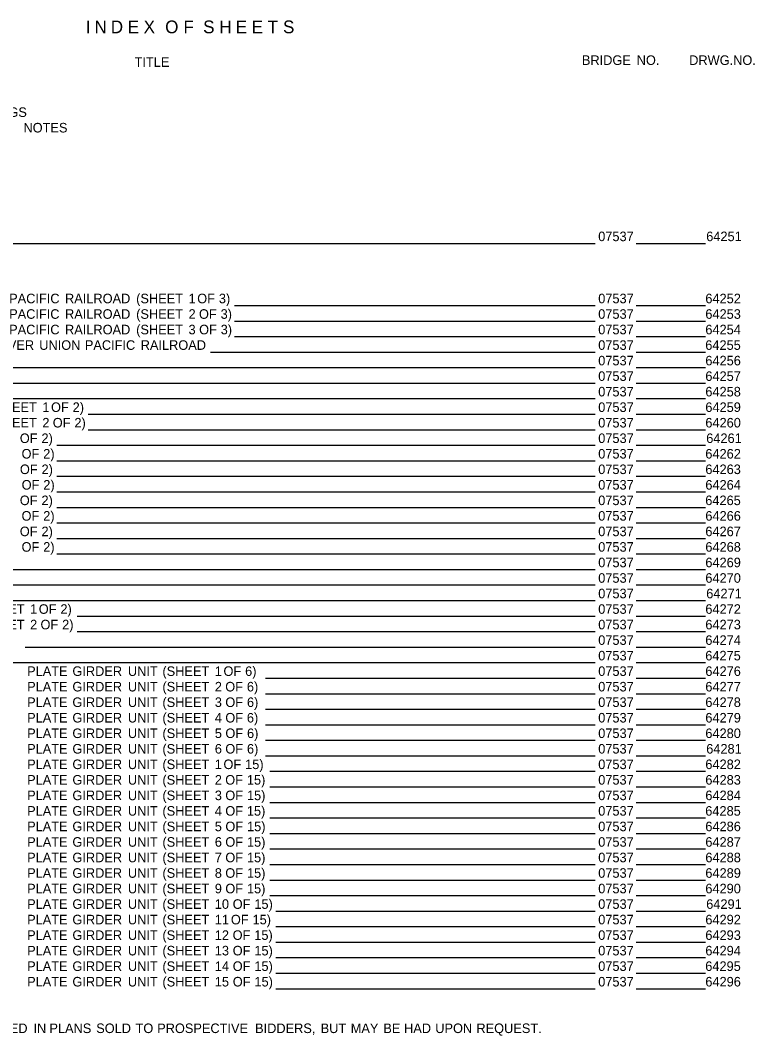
# Model space of a CAD drawing. Extents: x -1420 to 1630, y -1031 to 935.
# Drawn here: x -917 to 5, y -757 to 518 of the extents above; entities that cross this region are included whole.
import ezdxf

# ---------------------------------------------------------------- set-up
doc = ezdxf.new("R2010")
doc.units = 0
doc.layers.add('Default', color=7, linetype='Continuous')

msp = doc.modelspace()

# ---------------------------------------------------------------- linework, layer by layer
at = {"layer": 'Default'}
for p, q in [((-994.1, 238), (-195.2, 238)), ((-143.5, 238), (-56.7, 238)), ((-648.5, 160), (-195.2, 160)), ((-143.5, 160), (-56.7, 160)), ((-648.5, 140.5), (-195.2, 140.5)), ((-143.5, 140.5), (-56.7, 140.5)), ((-648.5, 121), (-195.2, 121)), ((-143.5, 121), (-56.7, 121)), ((-678.6, 101.5), (-195.2, 101.5)), ((-143.5, 101.5), (-56.7, 101.5)), ((-964.8, 82), (-195.2, 82)), ((-143.5, 82), (-56.7, 82)), ((-964.8, 62.5), (-195.2, 62.5)), ((-143.5, 62.5), (-56.7, 62.5)), ((-964.8, 43), (-195.2, 43)), ((-143.5, 43), (-56.7, 43)), ((-832.1, 23.5), (-195.2, 23.5)), ((-143.5, 23.5), (-56.7, 23.5)), ((-832.1, 4), (-195.2, 4)), ((-143.5, 4), (-56.7, 4)), ((-871.6, -15.5), (-195.2, -15.5)), ((-143.5, -15.5), (-56.7, -15.5)), ((-871.6, -35), (-195.2, -35)), ((-143.5, -35), (-56.7, -35)), ((-871.6, -54.5), (-195.2, -54.5)), ((-143.5, -54.5), (-56.7, -54.5)), ((-871.6, -74), (-195.2, -74)), ((-143.5, -74), (-56.7, -74)), ((-871.6, -93.5), (-195.2, -93.5)), ((-143.5, -93.5), (-56.7, -93.5)), ((-871.6, -113), (-195.2, -113)), ((-143.5, -113), (-56.7, -113)), ((-871.6, -132.5), (-195.2, -132.5)), ((-143.5, -132.5), (-56.7, -132.5)), ((-871.6, -152), (-195.2, -152)), ((-143.5, -152), (-56.7, -152)), ((-960.5, -171.5), (-195.2, -171.5)), ((-143.5, -171.5), (-56.7, -171.5)), ((-960.5, -191), (-195.2, -191)), ((-143.5, -191), (-56.7, -191)), ((-960.5, -210.5), (-195.2, -210.5)), ((-143.5, -210.5), (-56.7, -210.5)), ((-846.1, -230), (-195.2, -230)), ((-143.5, -230), (-56.7, -230)), ((-846.1, -249.5), (-195.2, -249.5)), ((-143.5, -249.5), (-56.7, -249.5)), ((-911.2, -269), (-195.2, -269)), ((-143.5, -269), (-56.7, -269)), ((-1055.5, -288.5), (-195.2, -288.5)), ((-143.5, -288.5), (-56.7, -288.5)), ((-609.3, -308), (-195.2, -308)), ((-143.5, -308), (-56.7, -308)), ((-609.3, -327.5), (-195.2, -327.5)), ((-143.5, -327.5), (-56.7, -327.5)), ((-609.3, -347), (-195.2, -347)), ((-143.5, -347), (-56.7, -347)), ((-609.3, -366.5), (-195.2, -366.5)), ((-143.5, -366.5), (-56.7, -366.5)), ((-609.3, -386), (-195.2, -386)), ((-143.5, -386), (-56.7, -386)), ((-609.3, -405.5), (-195.2, -405.5)), ((-143.5, -405.5), (-56.7, -405.5)), ((-603.8, -425), (-195.2, -425)), ((-143.5, -425), (-56.7, -425)), ((-603.8, -444.5), (-195.2, -444.5)), ((-143.5, -444.5), (-56.7, -444.5)), ((-603.8, -464), (-195.2, -464)), ((-143.5, -464), (-56.7, -464)), ((-603.8, -483.5), (-195.2, -483.5)), ((-143.5, -483.5), (-56.7, -483.5)), ((-603.8, -503), (-195.2, -503)), ((-143.5, -503), (-56.7, -503)), ((-603.8, -522.5), (-195.2, -522.5)), ((-143.5, -522.5), (-56.7, -522.5)), ((-603.8, -542), (-195.2, -542)), ((-143.5, -542), (-56.7, -542)), ((-603.8, -561.5), (-195.2, -561.5)), ((-143.5, -561.5), (-56.7, -561.5)), ((-603.8, -581), (-195.2, -581)), ((-143.5, -581), (-56.7, -581)), ((-596.3, -600.5), (-195.2, -600.5)), ((-143.5, -600.5), (-56.7, -600.5)), ((-596.3, -620), (-195.2, -620)), ((-143.5, -620), (-56.7, -620)), ((-596.3, -639.5), (-195.2, -639.5)), ((-143.5, -639.5), (-56.7, -639.5)), ((-596.3, -659), (-195.2, -659)), ((-143.5, -659), (-56.7, -659)), ((-596.3, -678.5), (-195.2, -678.5)), ((-143.5, -678.5), (-56.7, -678.5)), ((-596.3, -698), (-195.2, -698)), ((-143.5, -698), (-56.7, -698))]:
    msp.add_line(p, q, dxfattribs=at)

# ---------------------------------------------------------------- texts
for s, height, p in [('I', 16, (-835, 501.9)), (' N', 16, (-830.2, 501.9)), (' D', 16, (-809.7, 501.9)), (' E', 16, (-788.4, 501.9)), (' X', 16, (-768.4, 501.9)), ('  O', 16, (-747.3, 501.9)), (' F', 16, (-718.4, 501.9)), ('  S', 16, (-699.6, 501.9)), (' H', 16, (-673.3, 501.9)), (' E', 16, (-652.7, 501.9)), (' E', 16, (-632.7, 501.9)), (' T', 16, (-612.7, 501.9)), (' S', 16, (-593.3, 501.9)), ('BRIDGE', 12, (-211.8, 462.1)), (' NO.', 12, (-147.4, 462.1)), ('DRWG.NO.', 12, (-77, 462.1)), ('TITLE', 12, (-773.8, 459.7)), (' DRAWINGS', 12, (-1001.9, 396.8)), (' NOTES', 12, (-917.9, 377.3)), ('07537', 12, (-191.3, 240.8)), ('64251', 12, (-55.6, 240.8)), (' PACIFIC', 12, (-935.9, 162.8)), (' RAILROAD', 12, (-865.7, 162.8)), (' (SHEET', 12, (-776.3, 162.8)), (' 1', 12, (-710.5, 162.8)), (' OF', 12, (-699.6, 162.8)), (' 3)', 12, (-672.4, 162.8)), ('07537', 12, (-191.3, 162.8)), ('64252', 12, (-56.7, 162.8)), (' PACIFIC', 12, (-935.9, 143.3)), (' RAILROAD', 12, (-865.7, 143.3)), (' (SHEET', 12, (-776.3, 143.3)), (' 2', 12, (-710.5, 143.3)), (' OF', 12, (-697.4, 143.3)), (' 3)', 12, (-670.2, 143.3)), ('07537', 12, (-191.3, 143.3)), ('64253', 12, (-56.7, 143.3)), (' PACIFIC', 12, (-935.9, 123.8)), (' RAILROAD', 12, (-865.7, 123.8)), (' (SHEET', 12, (-776.3, 123.8)), (' 3', 12, (-710.5, 123.8)), (' OF', 12, (-697.2, 123.8)), (' 3)', 12, (-670.1, 123.8)), ('07537', 12, (-191.3, 123.8)), ('64254', 12, (-56.7, 123.8)), (' OVER', 12, (-950, 104.3)), (' UNION', 12, (-898.1, 104.3)), (' PACIFIC', 12, (-840.8, 104.3)), (' RAILROAD', 12, (-770.6, 104.3)), ('07537', 12, (-191.3, 104.3)), ('64255', 12, (-56.8, 104.3)), ('07537', 12, (-191.3, 84.8)), ('64256', 12, (-56.7, 84.8)), ('07537', 12, (-191.3, 65.3)), ('64257', 12, (-56.7, 65.3)), ('07537', 12, (-191.3, 45.8)), ('64258', 12, (-56.7, 45.8)), (' (SHEET', 12, (-960, 26.3)), (' 1', 12, (-894.2, 26.3)), (' OF', 12, (-883.3, 26.3)), (' 2)', 12, (-856.1, 26.3)), ('07537', 12, (-191.3, 26.3)), ('64259', 12, (-56.7, 26.3)), (' (SHEET', 12, (-960, 6.8)), (' 2', 12, (-894.2, 6.8)), (' OF', 12, (-881.1, 6.8)), (' 2)', 12, (-853.9, 6.8)), ('07537', 12, (-191.3, 6.8)), ('64260', 12, (-56.7, 6.8)), (' OF', 12, (-922.5, -12.7)), (' 2)', 12, (-895.3, -12.7)), ('07537', 12, (-191.3, -12.7)), ('64261', 12, (-55.6, -12.7)), (' OF', 12, (-920.3, -32.2)), (' 2)', 12, (-893.1, -32.2)), ('07537', 12, (-191.3, -32.2)), ('64262', 12, (-56.7, -32.2)), (' OF', 12, (-922.4, -51.7)), (' 2)', 12, (-895.2, -51.7)), ('07537', 12, (-191.3, -51.7)), ('64263', 12, (-56.7, -51.7)), (' OF', 12, (-920.2, -71.2)), (' 2)', 12, (-893, -71.2)), ('07537', 12, (-191.3, -71.2)), ('64264', 12, (-56.7, -71.2)), (' OF', 12, (-922.5, -90.7)), (' 2)', 12, (-895.3, -90.7)), ('07537', 12, (-191.3, -90.7)), ('64265', 12, (-56.8, -90.7)), (' OF', 12, (-920.3, -110.2)), (' 2)', 12, (-893.1, -110.2)), ('07537', 12, (-191.3, -110.2)), ('64266', 12, (-56.7, -110.2)), (' OF', 12, (-922.5, -129.7)), (' 2)', 12, (-895.3, -129.7)), ('07537', 12, (-191.3, -129.7)), ('64267', 12, (-56.7, -129.7)), (' OF', 12, (-920.3, -149.2)), (' 2)', 12, (-893.1, -149.2)), ('07537', 12, (-191.3, -149.2)), ('64268', 12, (-56.7, -149.2)), ('07537', 12, (-191.3, -168.7)), ('64269', 12, (-56.7, -168.7)), ('07537', 12, (-191.3, -188.2)), ('64270', 12, (-56.7, -188.2)), ('07537', 12, (-191.3, -207.7)), ('64271', 12, (-55.6, -207.7)), (' (SHEET', 12, (-975.4, -227.2)), (' 1', 12, (-909.6, -227.2)), (' OF', 12, (-898.7, -227.2)), (' 2)', 12, (-871.5, -227.2)), ('07537', 12, (-191.3, -227.2)), ('64272', 12, (-56.7, -227.2)), (' (SHEET', 12, (-975.4, -246.7)), (' 2', 12, (-909.6, -246.7)), (' OF', 12, (-896.5, -246.7)), (' 2)', 12, (-869.3, -246.7)), ('07537', 12, (-191.3, -246.7)), ('64273', 12, (-56.7, -246.7)), ('07537', 12, (-191.3, -266.2)), ('64274', 12, (-56.7, -266.2)), ('07537', 12, (-191.3, -285.7)), ('64275', 12, (-56.8, -285.7)), (' PLATE', 12, (-913.3, -305.2)), (' GIRDER', 12, (-856.4, -305.2)), (' UNIT', 12, (-786.7, -305.2)), (' (SHEET', 12, (-743.3, -305.2)), (' 1', 12, (-677.5, -305.2)), (' OF', 12, (-666.6, -305.2)), (' 6)', 12, (-639.4, -305.2)), ('07537', 12, (-191.3, -305.2)), ('64276', 12, (-56.7, -305.2)), (' PLATE', 12, (-913.3, -324.7)), (' GIRDER', 12, (-856.4, -324.7)), (' UNIT', 12, (-786.7, -324.7)), (' (SHEET', 12, (-743.3, -324.7)), (' 2', 12, (-677.5, -324.7)), (' OF', 12, (-664.4, -324.7)), (' 6)', 12, (-637.2, -324.7)), ('07537', 12, (-191.3, -324.7)), ('64277', 12, (-56.7, -324.7)), (' PLATE', 12, (-913.3, -344.2)), (' GIRDER', 12, (-856.4, -344.2)), (' UNIT', 12, (-786.7, -344.2)), (' (SHEET', 12, (-743.3, -344.2)), (' 3', 12, (-677.5, -344.2)), (' OF', 12, (-664.3, -344.2)), (' 6)', 12, (-637.1, -344.2)), ('07537', 12, (-191.3, -344.2)), ('64278', 12, (-56.7, -344.2)), (' PLATE', 12, (-913.3, -363.7)), (' GIRDER', 12, (-856.4, -363.7)), (' UNIT', 12, (-786.7, -363.7)), (' (SHEET', 12, (-743.3, -363.7)), (' 4', 12, (-677.5, -363.7)), (' OF', 12, (-664.3, -363.7)), (' 6)', 12, (-637.2, -363.7)), ('07537', 12, (-191.3, -363.7)), ('64279', 12, (-56.7, -363.7)), (' PLATE', 12, (-913.3, -383.2)), (' GIRDER', 12, (-856.4, -383.2)), (' UNIT', 12, (-786.7, -383.2)), (' (SHEET', 12, (-743.3, -383.2)), (' 5', 12, (-677.5, -383.2)), (' OF', 12, (-664.2, -383.2)), (' 6)', 12, (-637, -383.2)), ('07537', 12, (-191.3, -383.2)), ('64280', 12, (-56.7, -383.2)), (' PLATE', 12, (-913.3, -402.7)), (' GIRDER', 12, (-856.4, -402.7)), (' UNIT', 12, (-786.7, -402.7)), (' (SHEET', 12, (-743.3, -402.7)), (' 6', 12, (-677.5, -402.7)), (' OF', 12, (-664.3, -402.7)), (' 6)', 12, (-637.1, -402.7)), ('07537', 12, (-191.3, -402.7)), ('64281', 12, (-55.6, -402.7)), (' PLATE', 12, (-913.3, -422.2)), (' GIRDER', 12, (-856.4, -422.2)), (' UNIT', 12, (-786.7, -422.2)), (' (SHEET', 12, (-743.3, -422.2)), (' 1', 12, (-677.5, -422.2)), (' OF', 12, (-666.6, -422.2)), (' 15)', 12, (-639.4, -422.2)), ('07537', 12, (-191.3, -422.2)), ('64282', 12, (-56.7, -422.2)), (' PLATE', 12, (-913.3, -441.7)), (' GIRDER', 12, (-856.4, -441.7)), (' UNIT', 12, (-786.7, -441.7)), (' (SHEET', 12, (-743.3, -441.7)), (' 2', 12, (-677.5, -441.7)), (' OF', 12, (-664.4, -441.7)), (' 15)', 12, (-637.2, -441.7)), ('07537', 12, (-191.3, -441.7)), ('64283', 12, (-56.7, -441.7)), (' PLATE', 12, (-913.3, -461.2)), (' GIRDER', 12, (-856.4, -461.2)), (' UNIT', 12, (-786.7, -461.2)), (' (SHEET', 12, (-743.3, -461.2)), (' 3', 12, (-677.5, -461.2)), (' OF', 12, (-664.3, -461.2)), (' 15)', 12, (-637.1, -461.2)), ('07537', 12, (-191.3, -461.2)), ('64284', 12, (-56.7, -461.2)), (' PLATE', 12, (-913.3, -480.7)), (' GIRDER', 12, (-856.4, -480.7)), (' UNIT', 12, (-786.7, -480.7)), (' (SHEET', 12, (-743.3, -480.7)), (' 4', 12, (-677.5, -480.7)), (' OF', 12, (-664.3, -480.7)), (' 15)', 12, (-637.2, -480.7)), ('07537', 12, (-191.3, -480.7)), ('64285', 12, (-56.8, -480.7)), (' PLATE', 12, (-913.3, -500.2)), (' GIRDER', 12, (-856.4, -500.2)), (' UNIT', 12, (-786.7, -500.2)), (' (SHEET', 12, (-743.3, -500.2)), (' 5', 12, (-677.5, -500.2)), (' OF', 12, (-664.2, -500.2)), (' 15)', 12, (-637, -500.2)), ('07537', 12, (-191.3, -500.2)), ('64286', 12, (-56.7, -500.2)), (' PLATE', 12, (-913.3, -519.7)), (' GIRDER', 12, (-856.4, -519.7)), (' UNIT', 12, (-786.7, -519.7)), (' (SHEET', 12, (-743.3, -519.7)), (' 6', 12, (-677.5, -519.7)), (' OF', 12, (-664.3, -519.7)), (' 15)', 12, (-637.1, -519.7)), ('07537', 12, (-191.3, -519.7)), ('64287', 12, (-56.7, -519.7)), (' PLATE', 12, (-913.3, -539.2)), (' GIRDER', 12, (-856.4, -539.2)), (' UNIT', 12, (-786.7, -539.2)), (' (SHEET', 12, (-743.3, -539.2)), (' 7', 12, (-677.5, -539.2)), (' OF', 12, (-664.3, -539.2)), (' 15)', 12, (-637.1, -539.2)), ('07537', 12, (-191.3, -539.2)), ('64288', 12, (-56.7, -539.2)), (' PLATE', 12, (-913.3, -558.7)), (' GIRDER', 12, (-856.4, -558.7)), (' UNIT', 12, (-786.7, -558.7)), (' (SHEET', 12, (-743.3, -558.7)), (' 8', 12, (-677.5, -558.7)), (' OF', 12, (-664.3, -558.7)), (' 15)', 12, (-637.1, -558.7)), ('07537', 12, (-191.3, -558.7)), ('64289', 12, (-56.7, -558.7)), (' PLATE', 12, (-913.3, -578.2)), (' GIRDER', 12, (-856.4, -578.2)), (' UNIT', 12, (-786.7, -578.2)), (' (SHEET', 12, (-743.3, -578.2)), (' 9', 12, (-677.5, -578.2)), (' OF', 12, (-664.3, -578.2)), (' 15)', 12, (-637.1, -578.2)), ('07537', 12, (-191.3, -578.2)), ('64290', 12, (-56.7, -578.2)), (' PLATE', 12, (-913.3, -597.7)), (' GIRDER', 12, (-856.4, -597.7)), (' UNIT', 12, (-786.7, -597.7)), (' (SHEET', 12, (-743.3, -597.7)), (' 10', 12, (-677.5, -597.7)), (' OF', 12, (-655, -597.7)), (' 15)', 12, (-627.8, -597.7)), ('07537', 12, (-191.3, -597.7)), ('64291', 12, (-55.6, -597.7)), (' PLATE', 12, (-913.3, -617.2)), (' GIRDER', 12, (-856.4, -617.2)), (' UNIT', 12, (-786.7, -617.2)), (' (SHEET', 12, (-743.3, -617.2)), (' 11', 12, (-677.5, -617.2)), (' OF', 12, (-657.3, -617.2)), (' 15)', 12, (-630.1, -617.2)), ('07537', 12, (-191.3, -617.2)), ('64292', 12, (-56.7, -617.2)), (' PLATE', 12, (-913.3, -636.7)), (' GIRDER', 12, (-856.4, -636.7)), (' UNIT', 12, (-786.7, -636.7)), (' (SHEET', 12, (-743.3, -636.7)), (' 12', 12, (-677.5, -636.7)), (' OF', 12, (-655.1, -636.7)), (' 15)', 12, (-627.9, -636.7)), ('07537', 12, (-191.3, -636.7)), ('64293', 12, (-56.7, -636.7)), (' PLATE', 12, (-913.3, -656.2)), (' GIRDER', 12, (-856.4, -656.2)), (' UNIT', 12, (-786.7, -656.2)), (' (SHEET', 12, (-743.3, -656.2)), (' 13', 12, (-677.5, -656.2)), (' OF', 12, (-655, -656.2)), (' 15)', 12, (-627.8, -656.2)), ('07537', 12, (-191.3, -656.2)), ('64294', 12, (-56.7, -656.2)), (' (SHEET', 12, (-743.3, -675.7)), (' 15)', 12, (-627.8, -675.7)), (' PLATE', 12, (-913.3, -675.7)), (' GIRDER', 12, (-856.4, -675.7)), (' UNIT', 12, (-786.7, -675.7)), (' 14', 12, (-677.5, -675.7)), (' OF', 12, (-655, -675.7)), ('07537', 12, (-191.3, -675.7)), ('64295', 12, (-56.8, -675.7)), (' PLATE', 12, (-913.3, -695.2)), (' GIRDER', 12, (-856.4, -695.2)), (' UNIT', 12, (-786.7, -695.2)), (' (SHEET', 12, (-743.3, -695.2)), (' 15', 12, (-677.5, -695.2)), (' OF', 12, (-654.9, -695.2)), (' 15)', 12, (-627.7, -695.2)), ('07537', 12, (-191.3, -695.2)), ('64296', 12, (-56.7, -695.2)), (' INCLUDED', 12, (-994.8, -753.7)), (' IN', 12, (-905.3, -753.7)), (' PLANS', 12, (-885.3, -753.7)), (' SOLD', 12, (-826.5, -753.7)), (' TO', 12, (-777.1, -753.7)), (' PROSPECTIVE', 12, (-749.9, -753.7)), (' BIDDERS,', 12, (-626.9, -753.7)), (' BUT', 12, (-544.5, -753.7)), (' MAY', 12, (-506.7, -753.7)), (' BE', 12, (-465.8, -753.7)), (' HAD', 12, (-439.7, -753.7)), (' UPON', 12, (-400.5, -753.7)), (' REQUEST.', 12, (-348.8, -753.7))]:
    msp.add_text(s, height=height, dxfattribs=at).set_placement(p)

doc.saveas('drawing.dxf')
